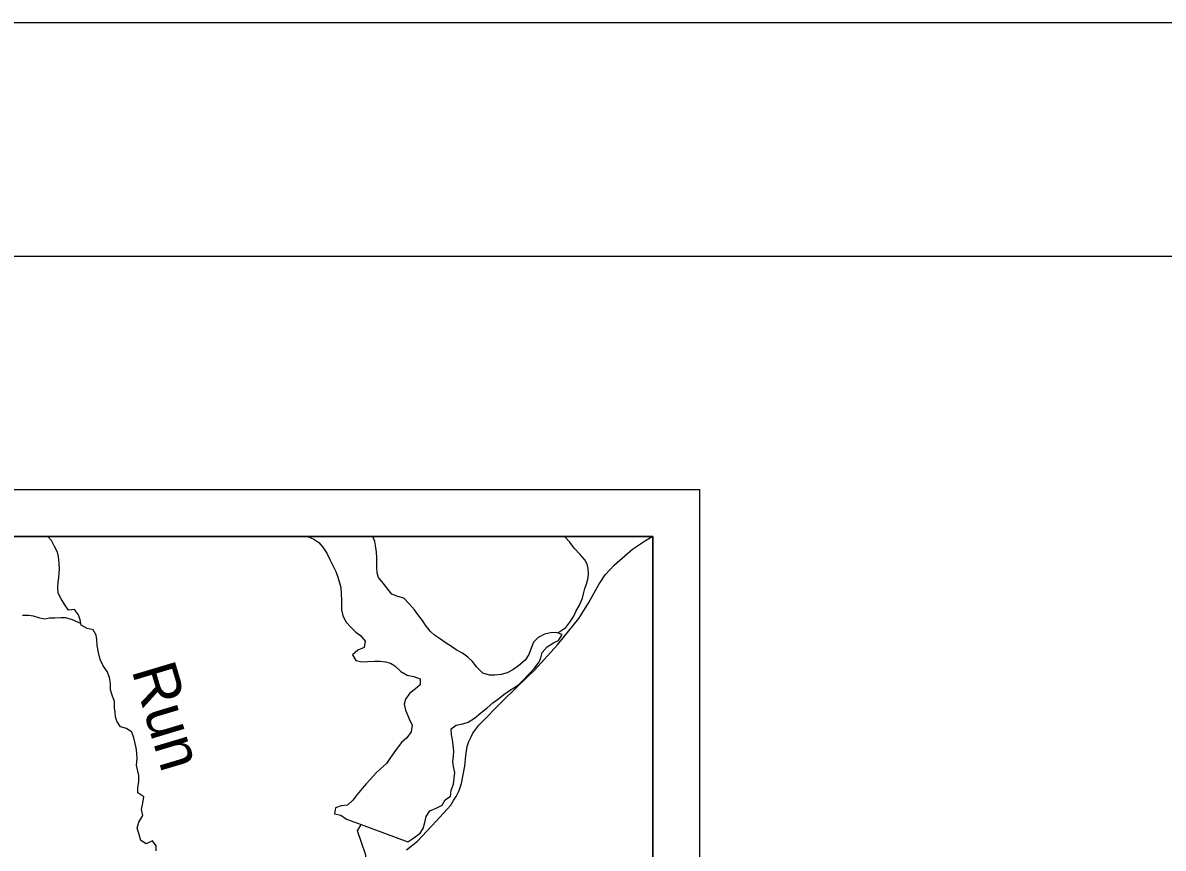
# Model space of a CAD drawing. Extents: x 0 to 34, y 0 to 22.
# Drawn here: x 7.55 to 9.993, y 20.232 to 22 of the extents above; entities that cross this region are included whole.
import ezdxf

# ---------------------------------------------------------------- set-up
doc = ezdxf.new("R2010")
doc.units = 0
for name, color, linetype in [('GM_X_Major_Lake', 7, 'Continuous'), ('GM_X_Major_River', 7, 'Continuous'), ('GM_X_Minor_River', 7, 'Continuous'), ('GM_X_Minor_River_Text', 7, 'Continuous'), ('GM_X_State_Route', 7, 'Continuous'), ('SC_Scratch1', 7, 'Continuous'), ('SH_Border', 7, 'Continuous'), ('SH_Cut_Line', 7, 'Continuous'), ('SH_Data', 7, 'Continuous')]:
    doc.layers.add(name, color=color, linetype=linetype)

msp = doc.modelspace()

# ---------------------------------------------------------------- linework, layer by layer
at = {"layer": 'GM_X_Major_Lake'}
for points in [[(8.1604, 20.9), (8.1607, 20.8997), (8.1736, 20.8937), (8.1843, 20.8868), (8.1926, 20.8769), (8.2013, 20.864), (8.2078, 20.8503), (8.2207, 20.8245), (8.2248, 20.8124), (8.2282, 20.8002), (8.2309, 20.7903), (8.232, 20.7767), (8.2324, 20.763), (8.2324, 20.7527), (8.2328, 20.7429), (8.2354, 20.7303), (8.2418, 20.7167), (8.254, 20.7041), (8.2635, 20.695), (8.2733, 20.6878), (8.2836, 20.6752), (8.2813, 20.662), (8.2676, 20.6563), (8.2562, 20.646), (8.2634, 20.6343), (8.2767, 20.6312), (8.2889, 20.6316), (8.3033, 20.6327), (8.3147, 20.6323), (8.3272, 20.6312), (8.3374, 20.6281), (8.3469, 20.6224), (8.3598, 20.6102), (8.3731, 20.6023), (8.3879, 20.6), (8.4015, 20.5946), (8.4011, 20.5821), (8.3909, 20.5734), (8.3791, 20.5643), (8.3696, 20.5514), (8.3673, 20.5404), (8.37, 20.5275), (8.3738, 20.5176), (8.3791, 20.5058), (8.3844, 20.496), (8.3817, 20.4815), (8.3726, 20.4683), (8.3609, 20.4584)], [(8.3748, 20.2458), (8.3877, 20.2541), (8.4014, 20.2644), (8.4078, 20.2739), (8.4116, 20.2871), (8.4143, 20.2997), (8.4219, 20.3122), (8.4355, 20.3179), (8.4481, 20.3239), (8.4545, 20.3357), (8.4659, 20.3436), (8.4674, 20.3566), (8.4727, 20.3695), (8.4743, 20.382), (8.4754, 20.3941), (8.4728, 20.407), (8.4716, 20.4169), (8.4728, 20.4298), (8.4732, 20.4401), (8.472, 20.453), (8.4705, 20.4651), (8.4686, 20.475), (8.4679, 20.4879), (8.4781, 20.4955), (8.4925, 20.4985), (8.5039, 20.5023), (8.5176, 20.5103), (8.5316, 20.5216), (8.5449, 20.533), (8.5571, 20.5432), (8.5673, 20.5508), (8.5806, 20.5611), (8.5927, 20.5698), (8.6022, 20.5755), (8.6117, 20.5819), (8.6227, 20.5929), (8.6353, 20.6062), (8.6459, 20.6176), (8.6554, 20.6297), (8.6596, 20.64), (8.663, 20.6513), (8.6732, 20.6635), (8.6869, 20.6718), (8.6975, 20.6771), (8.7055, 20.69), (8.6937, 20.6938), (8.6805, 20.6931), (8.6679, 20.6908), (8.6543, 20.6836), (8.644, 20.6734), (8.6391, 20.6605), (8.6338, 20.6468), (8.6262, 20.6351), (8.6121, 20.6229), (8.6, 20.6138), (8.5874, 20.6074), (8.5745, 20.6044), (8.5616, 20.6025), (8.5495, 20.6025), (8.5358, 20.6067), (8.523, 20.6196), (8.5131, 20.6317), (8.5036, 20.6409), (8.4919, 20.65), (8.4782, 20.6572), (8.4683, 20.6637), (8.457, 20.6713), (8.4448, 20.68), (8.4323, 20.6884), (8.4228, 20.6971), (8.413, 20.7097), (8.4061, 20.7195), (8.3963, 20.7325), (8.3891, 20.7423), (8.3777, 20.7556), (8.3663, 20.7674), (8.3534, 20.7708), (8.3402, 20.7762), (8.3322, 20.7868), (8.3223, 20.7994), (8.3121, 20.8115), (8.3094, 20.8221), (8.3087, 20.832), (8.3083, 20.8434), (8.3083, 20.8537), (8.3076, 20.8658), (8.3061, 20.8761), (8.3038, 20.889), (8.3001, 20.9)], [(8.3609, 20.4584), (8.3517, 20.4463), (8.3449, 20.436), (8.3377, 20.4265), (8.329, 20.4136), (8.3164, 20.4019), (8.3069, 20.3931), (8.2948, 20.3799), (8.2857, 20.3696), (8.277, 20.3598), (8.2659, 20.3469), (8.2568, 20.3351), (8.2458, 20.3245), (8.2322, 20.3226), (8.2196, 20.3188), (8.2174, 20.3059), (8.231, 20.3025), (8.2435, 20.2945)], [(8.2435, 20.2945), (8.2746, 20.283)], [(8.2746, 20.283), (8.3748, 20.2458)]]:
    msp.add_lwpolyline(points, dxfattribs=at)
at = {"layer": 'GM_X_Major_River'}
msp.add_lwpolyline([(8.3104, 20.0348), (8.3009, 20.0587), (8.2758, 20.0845), (8.2784, 20.1103), (8.2874, 20.1365), (8.2866, 20.1631), (8.2858, 20.1908), (8.2849, 20.217), (8.2754, 20.244), (8.267, 20.2694), (8.2746, 20.283)], dxfattribs=at)
at = {"layer": 'GM_X_Minor_River'}
for points in [[(7.7375, 20.5713), (7.7375, 20.585), (7.7352, 20.5975), (7.7307, 20.6104), (7.7219, 20.6229), (7.7155, 20.6362), (7.7121, 20.651), (7.7094, 20.6661), (7.7082, 20.679), (7.7071, 20.6885), (7.7003, 20.6999), (7.6874, 20.7029), (7.6749, 20.7094), (7.6726, 20.7215), (7.6688, 20.7321), (7.6605, 20.7431), (7.648, 20.742), (7.6396, 20.7533), (7.6317, 20.7658), (7.6256, 20.778), (7.6248, 20.7905), (7.6252, 20.8015), (7.6271, 20.8114), (7.6278, 20.8212), (7.6282, 20.8307), (7.6278, 20.8428), (7.6266, 20.8565), (7.624, 20.866), (7.6179, 20.8785), (7.6111, 20.8914), (7.6031, 20.9)], [(8.6962, 20.693), (8.7003, 20.6962), (8.7132, 20.7049), (8.7222, 20.7163), (8.7302, 20.7288), (8.7351, 20.7391), (8.743, 20.7524), (8.7494, 20.7675), (8.7513, 20.777), (8.7543, 20.788), (8.7574, 20.7975), (8.7611, 20.8112), (8.7619, 20.8206), (8.7615, 20.8309), (8.7592, 20.8404), (8.7543, 20.8498), (8.744, 20.8612), (8.7315, 20.8749), (8.722, 20.8878), (8.7122, 20.8984), (8.712, 20.9)], [(7.6742, 20.713), (7.6563, 20.7211), (7.6419, 20.7257), (7.6317, 20.7253), (7.6185, 20.7249), (7.6067, 20.7245), (7.5961, 20.7226), (7.5859, 20.7245), (7.573, 20.7287), (7.5624, 20.7305), (7.5488, 20.7302)], [(7.8356, 20.2267), (7.8356, 20.2373), (7.8276, 20.2475), (7.8144, 20.2411), (7.803, 20.2483), (7.7992, 20.2615), (7.7946, 20.2752), (7.7984, 20.2881), (7.8067, 20.3017), (7.8041, 20.3146), (7.8071, 20.3287), (7.809, 20.3423), (7.7961, 20.3503), (7.7961, 20.362), (7.7987, 20.3738), (7.7983, 20.3874), (7.7964, 20.3969), (7.7934, 20.4098), (7.7949, 20.4231), (7.7941, 20.4364), (7.7926, 20.447), (7.7907, 20.4565), (7.7876, 20.4686), (7.7834, 20.4807), (7.7721, 20.4887), (7.7588, 20.4917), (7.7512, 20.5038), (7.7486, 20.5137), (7.7474, 20.5236), (7.7463, 20.533), (7.7463, 20.5463), (7.7409, 20.5596), (7.7375, 20.5713)]]:
    msp.add_lwpolyline(points, dxfattribs=at)
at = {"layer": 'GM_X_State_Route'}
msp.add_lwpolyline([(8.3718, 20.2287), (8.3953, 20.247), (8.4355, 20.2902), (8.4588, 20.3158), (8.4672, 20.3244), (8.4728, 20.3343), (8.4785, 20.3428), (8.4849, 20.3555), (8.4896, 20.3709), (8.4926, 20.3854), (8.4969, 20.4078), (8.499, 20.4303), (8.5021, 20.4495), (8.5057, 20.4604), (8.5103, 20.4702), (8.5141, 20.4784), (8.5271, 20.4956), (8.5789, 20.5483), (8.6321, 20.5995), (8.6465, 20.6134), (8.6952, 20.6675), (8.7411, 20.7238), (8.7624, 20.7582), (8.7839, 20.7965), (8.7979, 20.8178), (8.8179, 20.8389), (8.8566, 20.8723), (8.8841, 20.891), (8.8981, 20.9)], dxfattribs=at)
at = {"layer": 'SC_Scratch1'}
msp.add_lwpolyline([(8.9, 18.7389), (8.9, 20.9), (5.53, 20.9), (5.4955, 20.3864), (5.4469, 19.6641), (5.4089, 19.0989), (5.4007, 18.9779), (5.4885, 18.9719), (5.9889, 18.9377), (6.8273, 18.8804), (7.2159, 18.8539), (8.2061, 18.7863)], close=True, dxfattribs=at)
at = {"layer": 'SH_Border'}
msp.add_lwpolyline([(1.5, 21.5), (33.5, 21.5), (33.5, 0.5), (1.5, 0.5)], close=True, dxfattribs=at)
at = {"layer": 'SH_Cut_Line'}
msp.add_lwpolyline([(0, 0), (34, 0), (34, 22), (0, 22)], close=True, dxfattribs=at)
at = {"layer": 'SH_Data'}
for p, q in [((2, 21), (9, 21)), ((9, 21), (9, 14)), ((2.1, 20.9), (8.9, 20.9)), ((8.9, 20.9), (8.9, 14.1))]:
    msp.add_line(p, q, dxfattribs=at)

# ---------------------------------------------------------------- texts
at = {"layer": 'GM_X_Minor_River_Text'}
msp.add_text('Run', height=0.09468, rotation=286.6623, dxfattribs=at).set_placement((7.7824, 20.6134))

doc.saveas('drawing.dxf')
